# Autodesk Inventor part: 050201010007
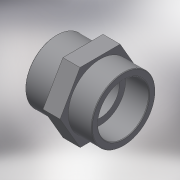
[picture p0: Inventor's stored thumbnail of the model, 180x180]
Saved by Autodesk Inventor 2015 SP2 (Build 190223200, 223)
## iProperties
Created: 2017-10
Part Number: 050201010007
Material: Generic
Description: PLASSON THREADED REDUCER PVC 1"-3/4"F
Document SubType Name: Modeling
Designer: KIM
Density: 1 g/cm^3
Appearance: Default
Author: KIM
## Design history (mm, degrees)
derived "050201.ipt"
feature "Solid1::050201.ipt"
tag "TaggingFeature1"
body "Solid1"
other parameters: "d0" = 48, "d1" = 24.117, "d2" = 36, "d4" = 19.2936, "d6" = 18, "d8" = 33.249, "d10" = 18, "d13" = 0, "d14" = 0.33249, "d15" = 12, "d16" = 26.5992, "d17" = 33.7638, "R_" = 33.249, "C_" = 36, "B_" = 12, "lt_" = 18, "H_" = 48, "G_" = 24.117
